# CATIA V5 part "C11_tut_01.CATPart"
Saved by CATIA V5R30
Part number: Part1
Bounding box of the stored display mesh (mm): x -74.488 to 0, y -50 to 50, z -100 to 0
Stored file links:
  D:\CADCIM\CATIA\2020\Ch11\c11_catia_v5_6r2019_tut\C11_tut_001.CATPart
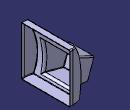
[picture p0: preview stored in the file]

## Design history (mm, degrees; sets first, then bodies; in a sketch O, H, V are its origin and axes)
Body1 (main body)
  Sketch1 on zx-plane, origin (0, 0, 0), H (-1, 0, 0), V (0, 0, 1)
    line L1 (0, 0) -> (12, 0)
    arc A1 centre (-96.8872, -61.3887) radius 125 from (12, 0) to (22, -100) cw
    line L2 (22, -100) -> (0, -100)
    point P4 (0, -100)
    length L1 = 12
    length L2 = 22
    distance L1 L2 = 100
    radius A1 = 125
    horizontal: L1 H, L2 H
    coincidence: P4 V
  Extrude1: Element1 Sketch1, Lim1 50, Lim2 50
  Sketch2 on zx-plane, origin (0, 0, 0), H (-1, 0, 0), V (0, 0, 1)
    line L1 (20, -40) -> (74.9495, -60)
    point P1 (20, -40)
    point P2 (74.9495, -60)
    reference projected line E1 (22, -100) -> (0, -100) from edge of Extrude1
    distance P2 H = 60
    distance P1 E1 = 60
    distance V P1 = 20
    angle L1 H = 20
  Plane1: type Normal, Curve Sketch2, RefPoint Sketch2.P2, Ratio 0
  Sketch3 on Plane1, origin (-85.4657, 0, -31.107), H (0, -1, 0), V (-0.342, 0, 0.9397)
    point P1 (-25, -30.7473)
    line L1 (-25, -30.7473) -> (25, -30.7473)
    line L2 (25, -30.7473) -> (25, -70.7473)
    line L3 (25, -70.7473) -> (-25, -70.7473)
    line L4 (-25, -70.7473) -> (-25, -30.7473)
    point P2 (25, -30.7473)
    reference projected point E1 (0, -30.7473) from Sketch2.P2
    axis line L5 (0, 21.6916) -> (0, -100.0328)
    point P5 (0, 21.6916)
    length L3 = 50
    length L2 = 40
    horizontal: L1 H, L3 H
    vertical: L2 V, L4 V, L5 V
    coincidence: L1 E1, P5 V
    symmetry: P1 P2 L5
  Plane2: type Normal, Curve Sketch2, RefPoint Sketch2.P1, Ratio 0
  Sketch4 on Plane2, origin (-30.5162, 0, -11.107), H (0, -1, 0), V (-0.342, 0, 0.9397)
    line L1 (-32.5, -21.2473) -> (32.5, -21.2473)
    line L2 (32.5, -21.2473) -> (32.5, -81.2473)
    line L3 (32.5, -81.2473) -> (-32.5, -81.2473)
    line L4 (-32.5, -81.2473) -> (-32.5, -21.2473)
    reference projected line E1 (25, -30.7473) -> (-25, -30.7473) from Sketch3.L1
    distance E1 L1 = 9.5
    distance V L2 = 32.5
    length L3 = 65
    length L2 = 60
    horizontal: L1 H, L3 H
    vertical: L2 V, L4 V
  Loft1: Sections (Sketch3; Sketch4), SectionCouplingPoints ({coupling CouplingPoints (vertex [element of Sketch3 | element of Sketch3]; vertex [element of Sketch4 | element of Sketch4])}; {coupling CouplingPoints (vertex [element of Sketch3 | element of Sketch3]; vertex [element of Sketch4 | element of Sketch4])}; {coupling CouplingPoints (vertex [element of Sketch3 | element of Sketch3]; vertex [element of Sketch4 | element of Sketch4])}; {coupling CouplingPoints (vertex [element of Sketch3 | element of Sketch3]; vertex [element of Sketch4 | element of Sketch4])})
  Sketch5 on face of Extrude1 from Sketch1.L1, origin (0, 0, 0), H (1, 0, 0), V (0, -1, 0)
    point P1 (0, -50)
    line L1 (0, -50) -> (-5, -50)
    reference projected point E1 (0, -50) from vertex [face of Extrude1 from Sketch1.L2]
    arc A1 centre (-5, 0) radius 50 from (-5, -50) to (-35.922, -39.2916) cw
    length L1 = 5
    radius A1 = 50
    horizontal: L1 H
    coincidence: P1 E1
    tangency: A1 L1
  Extrude2: Element1 Sketch5, Lim1 100, Lim2 0
  Symmetry1: Reference zx-plane, ToTransfor Extrude2
  Trim1: Trimmed (Extrude2; Extrude1)
  Trim2: Trimmed (Trim1; Symmetry1)
  Trim3: Trimmed (Loft1; Trim2)
  CloseSurface1: CloseElement Trim3
  Sketch6 on face of CloseSurface1, origin (-85.4657, 0, -31.107), H (0, -1, 0), V (-0.342, 0, 0.9397)
    line L1 (-20, -55.7473) -> (0, -55.7473)
    line L2 (0, -55.7473) -> (0, -65.7473)
    line L3 (0, -65.7473) -> (-20, -65.7473)
    line L4 (-20, -65.7473) -> (-20, -55.7473)
    reference projected line E1 (-25, -70.7473) -> (25, -70.7473) from edge [face of CloseSurface1 | face of CloseSurface1]
    reference projected line E2 (-25, -30.7473) -> (-25, -70.7473) from edge [face of CloseSurface1 | face of CloseSurface1]
    length L1 = 20
    length L4 = 10
    distance L3 E1 = 5
    distance L4 E2 = 5
    horizontal: L1 H, L3 H
    vertical: L2 V, L4 V
  Pocket1: profile Sketch6, direction (0.9397, 0, 0.342), length 5
  Fillet1: radius 1, on edge [face of CloseSurface1 | face of Pocket1 from Sketch6.L1]; edge [face of CloseSurface1 | face of Pocket1 from Sketch6.L2]; edge [face of CloseSurface1 | face of Pocket1 from Sketch6.L3]; edge [face of CloseSurface1 | face of Pocket1 from Sketch6.L4]; face of Pocket1 from Sketch6.L1; edge [face of Pocket1 from Sketch6.L1 | face of Pocket1 from Sketch6.L2]; edge [face of Pocket1 from Sketch6.L2 | end face of Pocket1]; edge [face of Pocket1 from Sketch6.L2 | face of Pocket1 from Sketch6.L3]; edge [face of Pocket1 from Sketch6.L3 | end face of Pocket1]; edge [face of Pocket1 from Sketch6.L3 | face of Pocket1 from Sketch6.L4]; edge [face of Pocket1 from Sketch6.L4 | end face of Pocket1]
  Fillet2: radius 3.5, on edge [face of CloseSurface1 | face of CloseSurface1] (x4)
  Fillet3: radius 2, on edge [face of CloseSurface1 | face of CloseSurface1] (x12)
  Fillet4: radius 2, on edge [face of CloseSurface1 | face of CloseSurface1] (x5); edge [face of CloseSurface1 | face of Fillet3]
  Shell1: ExtOffset 0, Face face of CloseSurface1, IntOffset 1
